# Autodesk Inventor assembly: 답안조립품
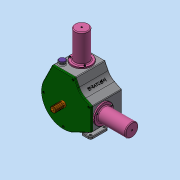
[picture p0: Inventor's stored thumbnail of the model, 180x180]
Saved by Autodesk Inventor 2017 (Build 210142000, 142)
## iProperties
Part Number: 답안조립품
Material: 일반
Document SubType Name: Assembly
Designer: MRC
Author: MRC
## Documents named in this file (13)
- C:\Users\MRC\Documents\Inventor\611109V1008\611109V1008 (1)\답안조립품.iam
- C:\Users\MRC\Documents\Inventor\611109V1008\611109V1008 (1)\본체.ipt
- C:\Users\MRC\Documents\Inventor\611109V1008\611109V1008 (1)\너트 M3.ipt
- C:\Users\MRC\Documents\Inventor\611109V1008\611109V1008 (1)\베어링 20 x 37 x 9.ipt
- C:\Users\MRC\Documents\Inventor\611109V1008\611109V1008 (1)\볼트 M3 x 12.ipt
- C:\Users\MRC\Documents\Inventor\611109V1008\611109V1008 (1)\실린더.ipt
- C:\Users\MRC\Documents\Inventor\611109V1008\611109V1008 (1)\앞커버.ipt
- C:\Users\MRC\Documents\Inventor\611109V1008\611109V1008 (1)\축.ipt
- C:\Users\MRC\Documents\Inventor\611109V1008\611109V1008 (1)\측정게이지.ipt
- C:\Users\MRC\Documents\Inventor\611109V1008\611109V1008 (1)\커넥팅로드 캡.ipt
- C:\Users\MRC\Documents\Inventor\611109V1008\611109V1008 (1)\커넥팅로드.ipt
- C:\Users\MRC\Documents\Inventor\611109V1008\611109V1008 (1)\피스톤 핀.ipt
- C:\Users\MRC\Documents\Inventor\611109V1008\611109V1008 (1)\피스톤.ipt
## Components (4 placed, 2 different names)
1. 피스톤 핀:1
2. 피스톤:1
3. 피스톤:2
4. 피스톤 핀:2
